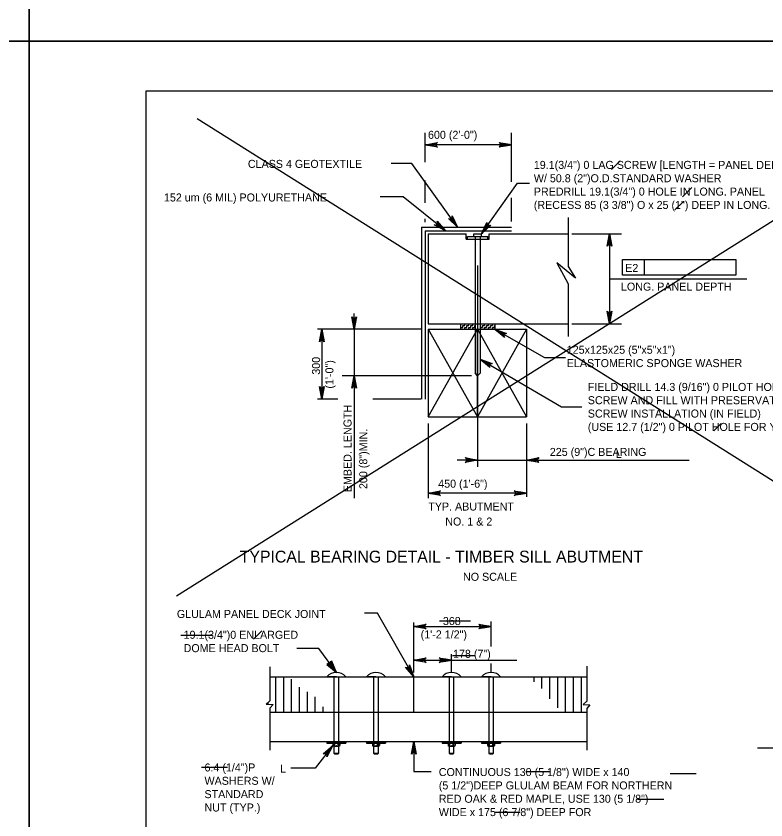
# Model space of a CAD drawing. Extents: x 179 to 454, y -271 to 54.
# Drawn here: x 243.55 to 254.79, y -121.67 to -109.62 of the extents above; entities that cross this region are included whole.
import ezdxf

# ---------------------------------------------------------------- set-up
doc = ezdxf.new("R2010")
doc.units = 0
for name, color, linetype in [('Level 1', 7, 'Continuous'), ('Level 2', 7, 'Continuous'), ('Level 3', 7, 'Continuous'), ('Level 4', 7, 'Continuous'), ('Level 41', 7, 'Continuous'), ('Level 5', 7, 'Continuous'), ('Level 62', 7, 'Continuous'), ('Level 63', 7, 'Continuous')]:
    doc.layers.add(name, color=color, linetype=linetype)

msp = doc.modelspace()

# ---------------------------------------------------------------- linework, layer by layer
at = {"layer": 'Level 1'}
msp.add_lwpolyline([(245.497, -131.25), (276.997, -131.25), (276.997, -110.75), (245.497, -110.75)], close=True, dxfattribs=at)
at = {"layer": 'Level 2'}
for p, q in [((249.627, -112.79), (249.627, -115.365)), ((249.627, -112.79), (250.976, -112.79)), ((249.682, -112.844), (249.682, -115.365)), ((249.682, -112.844), (250.976, -112.844)), ((249.725, -112.888), (249.725, -114.235)), ((249.725, -112.888), (250.295, -112.888)), ((250.295, -112.967), (250.295, -112.888)), ((250.295, -112.967), (250.643, -112.967)), ((250.315, -112.967), (250.315, -112.928)), ((250.315, -112.928), (250.623, -112.928)), ((250.41, -112.888), (250.528, -112.888)), ((250.41, -112.928), (250.41, -112.888)), ((250.43, -112.928), (250.43, -114.976)), ((250.508, -112.928), (250.508, -114.976)), ((250.528, -112.928), (250.528, -112.888)), ((250.623, -112.967), (250.623, -112.928)), ((250.643, -112.888), (251.819, -112.888)), ((250.643, -112.967), (250.643, -112.888)), ((250.469, -113.041), (250.469, -113.041)), ((249.725, -114.235), (251.819, -114.235)), ((250.213, -114.235), (250.213, -114.318)), ((250.213, -114.264), (250.218, -114.264)), ((250.218, -114.264), (250.218, -114.235)), ((250.218, -114.294), (250.248, -114.294)), ((250.218, -114.318), (250.218, -114.294)), ((250.248, -114.264), (250.277, -114.264)), ((250.248, -114.294), (250.248, -114.264)), ((250.277, -114.264), (250.277, -114.235)), ((250.277, -114.294), (250.307, -114.294)), ((250.277, -114.318), (250.277, -114.294)), ((250.307, -114.264), (250.336, -114.264)), ((250.307, -114.294), (250.307, -114.264)), ((250.336, -114.264), (250.336, -114.235)), ((250.336, -114.294), (250.366, -114.294)), ((250.336, -114.318), (250.336, -114.294)), ((250.366, -114.264), (250.395, -114.264)), ((250.366, -114.294), (250.366, -114.264)), ((250.395, -114.264), (250.395, -114.235)), ((250.395, -114.294), (250.425, -114.294)), ((250.395, -114.318), (250.395, -114.294)), ((250.425, -114.264), (250.43, -114.264)), ((250.425, -114.294), (250.425, -114.264)), ((250.508, -114.264), (250.514, -114.264)), ((250.514, -114.264), (250.514, -114.235)), ((250.514, -114.294), (250.543, -114.294)), ((250.514, -114.318), (250.514, -114.294)), ((250.543, -114.264), (250.573, -114.264)), ((250.543, -114.294), (250.543, -114.264)), ((250.573, -114.264), (250.573, -114.235)), ((250.573, -114.294), (250.602, -114.294)), ((250.573, -114.318), (250.573, -114.294)), ((250.602, -114.264), (250.632, -114.264)), ((250.602, -114.294), (250.602, -114.264)), ((250.632, -114.264), (250.632, -114.235)), ((250.632, -114.294), (250.661, -114.294)), ((250.632, -114.318), (250.632, -114.294)), ((250.661, -114.264), (250.691, -114.264)), ((250.661, -114.294), (250.661, -114.264)), ((250.691, -114.264), (250.691, -114.235)), ((250.691, -114.294), (250.72, -114.294)), ((250.691, -114.318), (250.691, -114.294)), ((250.72, -114.264), (250.725, -114.264)), ((250.72, -114.294), (250.72, -114.264)), ((250.725, -114.235), (250.725, -114.318)), ((249.725, -114.318), (249.725, -115.629)), ((249.725, -114.318), (251.202, -114.318)), ((249.726, -115.629), (250.469, -114.318)), ((250.469, -115.629), (250.469, -114.318)), ((250.469, -114.318), (251.202, -115.629)), ((251.202, -114.318), (250.469, -115.629)), ((251.202, -114.318), (251.202, -115.629)), ((249.726, -115.629), (251.202, -115.629)), ((248.091, -119.101), (247.758, -119.101)), ((248.351, -119.461), (248.091, -119.101)), ((252.105, -119.368), (252.105, -119.89)), ((247.354, -119.378), (247.354, -119.884)), ((247.354, -119.525), (252.105, -119.525)), ((248.351, -119.525), (248.208, -119.525)), ((248.32, -120.677), (248.32, -119.525)), ((248.351, -119.525), (248.494, -119.525)), ((248.383, -119.525), (248.383, -120.677)), ((248.913, -120.677), (248.913, -119.525)), ((248.976, -119.525), (248.976, -120.677)), ((249.511, -120.056), (249.511, -119.525)), ((250.046, -120.677), (250.046, -119.525)), ((250.109, -119.525), (250.109, -120.677)), ((250.64, -120.677), (250.64, -119.525)), ((250.703, -119.525), (250.703, -120.677)), ((247.354, -119.884), (247.299, -119.936)), ((247.299, -119.936), (247.403, -119.942)), ((247.403, -119.942), (247.354, -119.996)), ((252.105, -119.89), (252.049, -119.942)), ((252.049, -119.942), (252.153, -119.948)), ((252.153, -119.948), (252.105, -120.002)), ((247.354, -119.996), (247.354, -120.624)), ((247.354, -120.056), (252.105, -120.056)), ((252.105, -120.002), (252.105, -120.624)), ((247.354, -120.497), (252.105, -120.497)), ((248.299, -120.521), (248.299, -120.556)), ((248.403, -120.521), (248.299, -120.521)), ((248.299, -120.556), (248.314, -120.565)), ((248.314, -120.565), (248.388, -120.565)), ((248.327, -120.565), (248.327, -120.521)), ((248.376, -120.565), (248.376, -120.521)), ((248.388, -120.565), (248.403, -120.556)), ((248.403, -120.521), (248.403, -120.556)), ((248.997, -120.521), (248.892, -120.521)), ((248.892, -120.521), (248.892, -120.556)), ((248.892, -120.556), (248.907, -120.565)), ((248.907, -120.565), (248.982, -120.565)), ((248.92, -120.565), (248.92, -120.521)), ((248.969, -120.565), (248.969, -120.521)), ((248.982, -120.565), (248.997, -120.556)), ((248.997, -120.521), (248.997, -120.556)), ((250.13, -120.521), (250.026, -120.521)), ((250.026, -120.521), (250.026, -120.556)), ((250.026, -120.556), (250.041, -120.565)), ((250.041, -120.565), (250.115, -120.565)), ((250.053, -120.565), (250.053, -120.521)), ((250.102, -120.565), (250.102, -120.521)), ((250.115, -120.565), (250.13, -120.556)), ((250.13, -120.521), (250.13, -120.556)), ((250.723, -120.521), (250.619, -120.521)), ((250.619, -120.521), (250.619, -120.556)), ((250.619, -120.556), (250.634, -120.565)), ((250.634, -120.565), (250.708, -120.565)), ((250.647, -120.565), (250.647, -120.521)), ((250.696, -120.565), (250.696, -120.521)), ((250.708, -120.565), (250.723, -120.556)), ((250.723, -120.521), (250.723, -120.556)), ((248.327, -120.685), (248.32, -120.677)), ((248.383, -120.677), (248.32, -120.677)), ((248.375, -120.685), (248.327, -120.685)), ((248.383, -120.677), (248.375, -120.685)), ((248.976, -120.677), (248.913, -120.677)), ((248.921, -120.685), (248.913, -120.677)), ((248.968, -120.685), (248.921, -120.685)), ((248.976, -120.677), (248.968, -120.685)), ((250.109, -120.677), (250.046, -120.677)), ((250.054, -120.685), (250.046, -120.677)), ((250.101, -120.685), (250.054, -120.685)), ((250.109, -120.677), (250.101, -120.685)), ((250.703, -120.677), (250.64, -120.677)), ((250.647, -120.685), (250.64, -120.677)), ((250.695, -120.685), (250.647, -120.685)), ((250.703, -120.677), (250.695, -120.685))]:
    msp.add_line(p, q, dxfattribs=at)
msp.add_lwpolyline([(248.351, -119.461), (248.282, -119.289), (248.209, -119.341)], close=True, dxfattribs=at)
for centre, radius, start, end in [((248.351, -119.653), 0.192, 41.8701, 138.1299), ((248.325, -120.522), 0.0434, 233, 307), ((248.377, -120.522), 0.0434, 233, 307), ((248.918, -120.522), 0.0434, 233, 307), ((248.971, -120.522), 0.0434, 233, 307), ((250.052, -120.522), 0.0434, 233, 307), ((250.104, -120.522), 0.0434, 233, 307), ((250.645, -120.522), 0.0434, 233, 307), ((250.697, -120.522), 0.0434, 233, 307)]:
    msp.add_arc(centre, radius, start, end, dxfattribs=at)
at = {"layer": 'Level 3'}
for p, q in [((249.682, -111.814), (249.682, -111.373)), ((250.976, -112.111), (250.976, -111.373)), ((250.976, -111.553), (249.682, -111.553)), ((249.485, -111.835), (249.173, -111.835)), ((252.476, -111.925), (252.604, -111.796)), ((249.682, -112.423), (249.682, -112.089)), ((251.068, -112.131), (251.246, -112.131)), ((253.541, -112.335), (253.68, -112.196)), ((249.352, -112.333), (249.006, -112.333)), ((250.976, -112.701), (250.976, -112.348)), ((253.425, -112.53), (253.553, -112.401)), ((249.682, -112.711), (249.682, -112.661)), ((251.824, -112.645), (251.824, -113.376)), ((251.882, -112.888), (252.624, -112.888)), ((252.444, -112.888), (252.444, -114.235)), ((251.657, -113.324), (251.824, -113.636)), ((251.938, -113.553), (251.657, -113.324)), ((252.638, -113.272), (254.339, -113.272)), ((252.638, -113.508), (252.638, -113.272)), ((252.972, -113.508), (252.972, -113.272)), ((254.339, -113.272), (254.339, -113.508)), ((250.469, -113.363), (250.469, -116.38)), ((251.824, -113.376), (251.938, -113.553)), ((252.444, -113.561), (254.504, -113.561)), ((254.339, -113.508), (252.638, -113.508)), ((251.824, -113.636), (251.824, -114.428)), ((248.617, -114.318), (248.617, -114.082)), ((251.882, -114.235), (252.624, -114.235)), ((249.226, -114.318), (248.067, -114.318)), ((248.136, -114.318), (248.136, -115.365)), ((249.621, -114.318), (248.44, -114.318)), ((248.617, -114.318), (248.617, -115.016)), ((251.473, -114.74), (251.785, -114.74)), ((250.377, -115.016), (248.44, -115.016)), ((248.617, -115.016), (248.617, -116.851)), ((248.374, -115.365), (248.067, -115.365)), ((249.619, -115.365), (248.896, -115.365)), ((251.728, -115.482), (252.03, -115.482)), ((249.726, -115.728), (249.726, -116.849)), ((251.202, -115.728), (251.202, -116.83)), ((254.011, -115.84), (254.119, -115.731)), ((251.202, -116.137), (251.202, -116.332)), ((250.31, -116.277), (250.163, -116.277)), ((250.429, -116.277), (251.438, -116.277)), ((251.438, -116.277), (253.641, -116.277)), ((251.202, -116.775), (249.725, -116.775)), ((247.109, -118.961), (247.232, -118.839)), ((248.033, -120.894), (247.671, -120.894)), ((249.511, -120.945), (249.773, -120.945))]:
    msp.add_line(p, q, dxfattribs=at)
for points in [[(249.682, -111.553), (249.868, -111.519), (249.854, -111.528), (249.846, -111.541), (249.844, -111.553), (249.846, -111.566), (249.854, -111.578), (249.868, -111.588), (249.682, -111.553), (249.854, -111.578), (249.846, -111.566), (249.682, -111.553), (249.844, -111.553), (249.846, -111.541), (249.682, -111.553), (249.854, -111.528)], [(250.976, -111.553), (250.79, -111.588), (250.804, -111.578), (250.812, -111.566), (250.814, -111.553), (250.812, -111.541), (250.804, -111.528), (250.79, -111.519), (250.976, -111.553), (250.804, -111.528), (250.812, -111.541), (250.976, -111.553), (250.814, -111.553), (250.812, -111.566), (250.976, -111.553), (250.804, -111.578)], [(250.168, -112.79), (249.485, -111.835)], [(250.528, -112.888), (251.068, -112.131)], [(249.986, -112.844), (249.352, -112.333)], [(250.168, -112.79), (250.031, -112.659), (250.048, -112.665), (250.062, -112.663), (250.074, -112.658), (250.083, -112.649), (250.088, -112.636), (250.088, -112.618), (250.168, -112.79), (250.088, -112.636), (250.083, -112.649), (250.168, -112.79), (250.074, -112.658), (250.062, -112.663), (250.168, -112.79), (250.048, -112.665)], [(249.986, -112.844), (249.819, -112.755), (249.836, -112.756), (249.85, -112.751), (249.859, -112.742), (249.866, -112.731), (249.868, -112.717), (249.863, -112.7), (249.986, -112.844), (249.868, -112.717), (249.866, -112.731), (249.986, -112.844), (249.859, -112.742), (249.85, -112.751), (249.986, -112.844), (249.836, -112.756)], [(250.528, -112.888), (250.608, -112.716), (250.608, -112.734), (250.613, -112.747), (250.622, -112.756), (250.634, -112.761), (250.648, -112.763), (250.665, -112.757), (250.528, -112.888), (250.648, -112.763), (250.634, -112.761), (250.528, -112.888), (250.622, -112.756), (250.613, -112.747), (250.528, -112.888), (250.608, -112.734)], [(252.444, -112.888), (252.479, -113.075), (252.469, -113.06), (252.457, -113.053), (252.444, -113.051), (252.432, -113.053), (252.419, -113.06), (252.409, -113.075), (252.444, -112.888), (252.419, -113.06), (252.432, -113.053), (252.444, -112.888), (252.444, -113.051), (252.457, -113.053), (252.444, -112.888), (252.469, -113.06)], [(252.444, -114.235), (252.409, -114.048), (252.419, -114.063), (252.432, -114.07), (252.444, -114.072), (252.457, -114.07), (252.469, -114.063), (252.479, -114.048), (252.444, -114.235), (252.469, -114.063), (252.457, -114.07), (252.444, -114.235), (252.444, -114.072), (252.432, -114.07), (252.444, -114.235), (252.419, -114.063)], [(248.617, -114.318), (248.583, -114.132), (248.593, -114.146), (248.605, -114.153), (248.617, -114.155), (248.63, -114.153), (248.642, -114.146), (248.652, -114.132), (248.617, -114.318), (248.642, -114.146), (248.63, -114.153), (248.617, -114.318), (248.617, -114.155), (248.605, -114.153), (248.617, -114.318), (248.593, -114.146)], [(248.136, -114.318), (248.171, -114.504), (248.161, -114.49), (248.149, -114.483), (248.136, -114.48), (248.124, -114.483), (248.111, -114.49), (248.101, -114.504), (248.136, -114.318), (248.111, -114.49), (248.124, -114.483), (248.136, -114.318), (248.136, -114.48), (248.149, -114.483), (248.136, -114.318), (248.161, -114.49)], [(250.725, -114.318), (251.473, -114.74)], [(250.725, -114.318), (250.904, -114.379), (250.887, -114.381), (250.874, -114.388), (250.866, -114.398), (250.862, -114.41), (250.862, -114.424), (250.87, -114.44), (250.725, -114.318), (250.862, -114.424), (250.862, -114.41), (250.725, -114.318), (250.866, -114.398), (250.874, -114.388), (250.725, -114.318), (250.887, -114.381)], [(250.508, -114.768), (251.728, -115.482)], [(250.508, -114.768), (250.687, -114.832), (250.67, -114.834), (250.657, -114.841), (250.649, -114.85), (250.644, -114.862), (250.644, -114.877), (250.652, -114.893), (250.508, -114.768), (250.644, -114.877), (250.644, -114.862), (250.508, -114.768), (250.649, -114.85), (250.657, -114.841), (250.508, -114.768), (250.67, -114.834)], [(248.617, -115.016), (248.652, -115.202), (248.642, -115.188), (248.63, -115.18), (248.617, -115.178), (248.605, -115.18), (248.593, -115.188), (248.583, -115.202), (248.617, -115.016), (248.593, -115.188), (248.605, -115.18), (248.617, -115.016), (248.617, -115.178), (248.63, -115.18), (248.617, -115.016), (248.642, -115.188)], [(248.136, -115.365), (248.101, -115.178), (248.111, -115.192), (248.124, -115.2), (248.136, -115.202), (248.149, -115.2), (248.161, -115.192), (248.171, -115.178), (248.136, -115.365), (248.161, -115.192), (248.149, -115.2), (248.136, -115.365), (248.136, -115.202), (248.124, -115.2), (248.136, -115.365), (248.111, -115.192)], [(250.469, -116.277), (250.283, -116.312), (250.297, -116.302), (250.304, -116.29), (250.307, -116.277), (250.304, -116.265), (250.297, -116.252), (250.283, -116.242), (250.469, -116.277), (250.297, -116.252), (250.304, -116.265), (250.469, -116.277), (250.307, -116.277), (250.304, -116.29), (250.469, -116.277), (250.297, -116.302)], [(251.202, -116.277), (251.388, -116.242), (251.374, -116.252), (251.367, -116.265), (251.364, -116.277), (251.367, -116.29), (251.374, -116.302), (251.388, -116.312), (251.202, -116.277), (251.374, -116.302), (251.367, -116.29), (251.202, -116.277), (251.364, -116.277), (251.367, -116.265), (251.202, -116.277), (251.374, -116.252)], [(249.725, -116.775), (249.912, -116.74), (249.898, -116.75), (249.89, -116.762), (249.888, -116.775), (249.89, -116.787), (249.898, -116.8), (249.912, -116.809), (249.725, -116.775), (249.898, -116.8), (249.89, -116.787), (249.725, -116.775), (249.888, -116.775), (249.89, -116.762), (249.725, -116.775), (249.898, -116.75)], [(251.202, -116.775), (251.016, -116.809), (251.03, -116.8), (251.037, -116.787), (251.039, -116.775), (251.037, -116.762), (251.03, -116.75), (251.016, -116.74), (251.202, -116.775), (251.03, -116.75), (251.037, -116.762), (251.202, -116.775), (251.039, -116.775), (251.037, -116.787), (251.202, -116.775), (251.03, -116.8)], [(249.511, -119.525), (248.97, -118.57), (248.773, -118.57)], [(248.351, -119.461), (248.214, -119.33), (248.23, -119.336), (248.245, -119.335), (248.256, -119.329), (248.265, -119.32), (248.271, -119.307), (248.27, -119.289), (248.351, -119.461), (248.271, -119.307), (248.265, -119.32), (248.351, -119.461), (248.256, -119.329), (248.245, -119.335), (248.351, -119.461), (248.23, -119.336)], [(249.511, -119.525), (249.389, -119.379), (249.405, -119.387), (249.42, -119.388), (249.431, -119.383), (249.441, -119.375), (249.449, -119.363), (249.45, -119.345), (249.511, -119.525), (249.449, -119.363), (249.441, -119.375), (249.511, -119.525), (249.431, -119.383), (249.42, -119.388), (249.511, -119.525), (249.405, -119.387)], [(248.299, -120.556), (248.033, -120.894)], [(248.299, -120.556), (248.211, -120.725), (248.212, -120.707), (248.207, -120.694), (248.198, -120.684), (248.187, -120.678), (248.173, -120.676), (248.156, -120.681), (248.299, -120.556), (248.173, -120.676), (248.187, -120.678), (248.299, -120.556), (248.198, -120.684), (248.207, -120.694), (248.299, -120.556), (248.212, -120.707)], [(249.511, -120.497), (249.546, -120.684), (249.536, -120.669), (249.524, -120.662), (249.511, -120.66), (249.499, -120.662), (249.486, -120.669), (249.476, -120.684), (249.511, -120.497), (249.486, -120.669), (249.499, -120.662), (249.511, -120.497), (249.511, -120.66), (249.524, -120.662), (249.511, -120.497), (249.536, -120.669)], [(249.511, -120.497), (249.511, -120.945)]]:
    msp.add_lwpolyline(points, dxfattribs=at)
for points in [[(249.802, -111.533), (249.802, -111.573), (249.682, -111.553)], [(250.856, -111.533), (250.856, -111.573), (250.976, -111.553)], [(252.424, -113.008), (252.464, -113.008), (252.444, -112.888)], [(252.424, -114.115), (252.464, -114.115), (252.444, -114.235)], [(248.598, -114.2), (248.637, -114.2), (248.617, -114.318)], [(248.116, -114.438), (248.156, -114.438), (248.136, -114.318)], [(248.116, -115.245), (248.156, -115.245), (248.136, -115.365)], [(250.31, -116.258), (250.31, -116.297), (250.429, -116.277)], [(251.32, -116.258), (251.32, -116.297), (251.202, -116.277)], [(249.844, -116.755), (249.844, -116.794), (249.725, -116.775)], [(251.084, -116.755), (251.084, -116.794), (251.202, -116.775)], [(249.511, -119.525), (249.509, -119.521), (249.507, -119.522)], [(248.299, -120.556), (248.295, -120.559), (248.297, -120.561)], [(249.511, -120.497), (249.51, -120.502), (249.512, -120.502)]]:
    msp.add_lwpolyline(points, close=True, dxfattribs=at)
at = {"layer": 'Level 41'}
for p, q in [((257.335, -111.161), (245.957, -118.316)), ((246.267, -111.161), (257.645, -118.316)), ((249.898, -118.687), (250.363, -118.687)), ((246.019, -118.904), (246.484, -118.904)), ((250.094, -119.205), (250.425, -119.205)), ((246.329, -120.882), (246.722, -120.882)), ((251.191, -120.944), (251.553, -120.944)), ((253.353, -120.975), (253.746, -120.975)), ((252.867, -121.358), (253.26, -121.358)), ((250.725, -121.554), (251.108, -121.554))]:
    msp.add_line(p, q, dxfattribs=at)
at = {"layer": 'Level 5'}
for p, q in [((249.726, -114.318), (250.469, -115.629)), ((250.469, -115.016), (250.43, -114.976)), ((250.469, -115.016), (250.508, -114.976)), ((249.511, -119.463), (249.511, -118.711)), ((249.511, -119.463), (249.511, -118.725)), ((250.671, -119.074), (250.671, -118.697)), ((249.511, -118.774), (250.671, -118.774)), ((250.671, -118.774), (250.671, -118.774)), ((249.511, -119.463), (249.511, -119.097)), ((250.078, -119.463), (250.078, -119.186)), ((249.511, -119.275), (251.055, -119.275)), ((250.078, -119.274), (250.078, -119.274)), ((250.671, -119.463), (250.671, -119.326)), ((247.445, -120.056), (247.445, -119.525)), ((247.563, -120.056), (247.563, -119.525)), ((247.681, -120.056), (247.681, -119.559)), ((248.945, -119.525), (248.802, -119.525)), ((248.945, -119.525), (249.087, -119.525)), ((249.511, -119.525), (249.511, -119.525)), ((250.078, -119.525), (249.935, -119.525)), ((250.078, -119.525), (250.078, -119.525)), ((250.078, -119.525), (250.22, -119.525)), ((250.671, -119.525), (250.528, -119.525)), ((250.671, -119.525), (250.671, -119.525)), ((250.671, -119.525), (250.814, -119.525)), ((251.315, -119.6), (251.315, -119.525)), ((251.433, -119.701), (251.433, -119.525)), ((251.552, -119.854), (251.552, -119.525)), ((251.67, -119.991), (251.67, -119.525)), ((251.788, -120.054), (251.788, -119.525)), ((251.906, -120.056), (251.906, -119.525)), ((252.024, -120.056), (252.024, -119.525)), ((247.799, -120.056), (247.799, -119.679)), ((247.917, -120.056), (247.917, -119.751)), ((248.036, -120.056), (248.036, -119.828)), ((247.327, -119.938), (247.327, -119.91)), ((252.142, -119.961), (252.142, -119.947)), ((248.154, -120.056), (248.154, -119.974)), ((248.272, -120.056), (248.272, -120.051)), ((250.917, -120.056), (250.917, -120.056)), ((248.208, -120.497), (248.208, -120.521)), ((248.208, -120.509), (248.494, -120.509)), ((248.208, -120.521), (248.494, -120.521)), ((248.494, -120.497), (248.494, -120.521)), ((248.802, -120.497), (248.802, -120.521)), ((248.802, -120.509), (249.087, -120.509)), ((248.802, -120.521), (249.087, -120.521)), ((249.087, -120.497), (249.087, -120.521)), ((249.935, -120.497), (249.935, -120.521)), ((249.935, -120.509), (250.22, -120.509)), ((249.935, -120.521), (250.22, -120.521)), ((250.22, -120.497), (250.22, -120.521)), ((250.528, -120.497), (250.528, -120.521)), ((250.528, -120.509), (250.814, -120.509)), ((250.528, -120.521), (250.814, -120.521)), ((250.814, -120.497), (250.814, -120.521)), ((256.371, -120.593), (254.664, -120.593))]:
    msp.add_line(p, q, dxfattribs=at)
for points in [[(249.511, -118.774), (249.698, -118.739), (249.683, -118.749), (249.676, -118.762), (249.674, -118.774), (249.676, -118.787), (249.683, -118.799), (249.698, -118.809), (249.511, -118.774), (249.683, -118.799), (249.676, -118.787), (249.511, -118.774), (249.674, -118.774), (249.676, -118.762), (249.511, -118.774), (249.683, -118.749)], [(250.671, -118.774), (250.485, -118.809), (250.499, -118.799), (250.506, -118.787), (250.509, -118.774), (250.506, -118.762), (250.499, -118.749), (250.485, -118.739), (250.671, -118.774), (250.499, -118.749), (250.506, -118.762), (250.671, -118.774), (250.509, -118.774), (250.506, -118.787), (250.671, -118.774), (250.499, -118.799)], [(249.511, -119.274), (249.698, -119.24), (249.683, -119.249), (249.676, -119.262), (249.674, -119.274), (249.676, -119.287), (249.683, -119.299), (249.698, -119.309), (249.511, -119.274), (249.683, -119.299), (249.676, -119.287), (249.511, -119.274), (249.674, -119.274), (249.676, -119.262), (249.511, -119.274), (249.683, -119.249)], [(250.078, -119.274), (249.891, -119.309), (249.906, -119.299), (249.913, -119.287), (249.915, -119.274), (249.913, -119.262), (249.906, -119.249), (249.891, -119.24), (250.078, -119.274), (249.906, -119.249), (249.913, -119.262), (250.078, -119.274), (249.915, -119.274), (249.913, -119.287), (250.078, -119.274), (249.906, -119.299)]]:
    msp.add_lwpolyline(points, dxfattribs=at)
for points in [[(249.629, -118.755), (249.629, -118.794), (249.511, -118.774)], [(250.553, -118.755), (250.553, -118.794), (250.671, -118.774)], [(249.629, -119.255), (249.629, -119.294), (249.511, -119.274)], [(249.96, -119.255), (249.96, -119.294), (250.078, -119.274)]]:
    msp.add_lwpolyline(points, close=True, dxfattribs=at)
for centre in [(248.945, -119.653), (250.078, -119.653), (250.671, -119.653)]:
    msp.add_arc(centre, 0.192, 41.8701, 138.1299, dxfattribs=at)
at = {"layer": 'Level 62'}
msp.add_line((243.747, -110), (243.747, -110), dxfattribs=at)
at = {"layer": 'Level 63'}
for points in [[(209.747, -110), (243.747, -110), (243.747, -88), (209.747, -88)], [(243.747, -110), (277.747, -110), (277.747, -88), (243.747, -88)], [(209.747, -132), (243.747, -132), (243.747, -110), (209.747, -110)], [(243.747, -132), (277.747, -132), (277.747, -110), (243.747, -110)]]:
    msp.add_lwpolyline(points, close=True, dxfattribs=at)

# ---------------------------------------------------------------- texts
at = {"layer": 'Level 2'}
msp.add_text('TYPICAL BEARING DETAIL - TIMBER SILL ABUTMENT', height=0.17717, dxfattribs=at).set_placement((246.904, -117.813))
at = {"layer": 'Level 3'}
for s, p in [('600 (2\'-0")', (249.725, -111.464)), ('CLASS 4 GEOTEXTILE', (247.025, -111.9)), ('19.1(3/4") 0 LAG SCREW [LENGTH = PANEL DEPTH + 200(8")]', (251.311, -111.915)), ('W/ 50.8 (2")O.D.STANDARD WASHER', (251.311, -112.115)), ('PREDRILL 19.1(3/4") 0 HOLE IN LONG. PANEL', (251.311, -112.315)), ('152 um (6 MIL) POLYURETHANE', (245.767, -112.403)), ('(RECESS 85 (3 3/8") O x 25 (1") DEEP IN LONG. PANEL)', (251.311, -112.515)), ('E2', (252.681, -113.459)), ('LONG. PANEL DEPTH', (252.617, -113.739)), ('FIELD DRILL 14.3 (9/16") 0 PILOT HOLE FOR LAG', (252.12, -115.242)), ('SCREW AND FILL WITH PRESERVATIVE PRIOR TO', (252.12, -115.441)), ('SCREW INSTALLATION (IN FIELD)', (252.12, -115.641)), ('(USE 12.7 (1/2") 0 PILOT HOLE FOR YELLOW POPLAR)', (252.12, -115.841)), ('225 (9")C BEARING', (251.551, -116.216)), ('L', (252.541, -116.245)), ('450 (1\'-6")', (249.878, -116.692)), ('TYP. ABUTMENT', (249.729, -117.034)), ('NO. 1 & 2', (249.984, -117.259)), ('NO SCALE', (250.25, -118.087)), ('GLULAM PANEL DECK JOINT', (245.961, -118.644)), ('19.1(3/4")0 ENLARGED', (246.062, -118.956)), ('DOME HEAD BOLT', (246.062, -119.156)), ('6.4 (1/4")P', (246.375, -120.944)), ('L', (247.506, -120.961)), ('CONTINUOUS 130 (5 1/8") WIDE x 140', (249.887, -121.013)), ('WASHERS W/ ', (246.375, -121.144)), ('(5 1/2")DEEP GLULAM BEAM FOR NORTHERN', (249.887, -121.213)), ('STANDARD', (246.375, -121.344)), ('RED OAK & RED MAPLE, USE 130 (5 1/8")', (249.887, -121.413)), ('NUT (TYP.)', (246.375, -121.544)), ('WIDE x 175 (6 7/8") DEEP FOR', (249.887, -121.613))]:
    msp.add_text(s, height=0.12, dxfattribs=at).set_placement(p)
for s, p in [('300', (248.107, -114.999)), ('(1\'-0")', (248.307, -115.207)), ('EMBED. LENGTH', (248.579, -116.759)), ('200 (8")MIN.', (248.814, -116.712))]:
    msp.add_text(s, height=0.12, rotation=90, dxfattribs=at).set_placement(p)
at = {"layer": 'Level 4'}
for s, p in [('125x125x25 (5"x5"x1")', (251.805, -114.685)), ('ELASTOMERIC SPONGE WASHER', (251.805, -114.885))]:
    msp.add_text(s, height=0.12, dxfattribs=at).set_placement(p)
at = {"layer": 'Level 5'}
for s, p in [('368', (249.948, -118.75)), ('(1\'-2 1/2")', (249.615, -118.95)), ('178 (7")', (250.1, -119.241))]:
    msp.add_text(s, height=0.12, dxfattribs=at).set_placement(p)

doc.saveas('drawing.dxf')
